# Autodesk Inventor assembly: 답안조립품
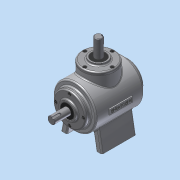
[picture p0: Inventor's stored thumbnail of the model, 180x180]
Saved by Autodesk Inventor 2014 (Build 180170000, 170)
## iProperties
Created: 2015-01
Part Number: 답안조립품
Document SubType Name: Assembly
Designer: user
Author: user
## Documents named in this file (15)
- C:\Users\user\Desktop\450105V1031\답안조립품.iam
- C:\Users\user\Desktop\450105V1031\본체.ipt
- C:\Users\user\Desktop\450105V1031\커버2.ipt
- C:\Users\user\Desktop\450105V1031\M4.ipt
- C:\Users\user\Desktop\450105V1031\서브 축.ipt
- 서브 축.ipt
- C:\Users\user\Desktop\450105V1031\키 4x4.ipt
- C:\Users\user\Desktop\450105V1031\서브 베벨기어.ipt
- C:\Users\user\Desktop\450105V1031\베어링 6203.ipt
- C:\Users\user\Desktop\450105V1031\커버.ipt
- C:\Users\user\Desktop\450105V1031\오일실.ipt
- C:\Users\user\Desktop\450105V1031\메인 축.ipt
- 메인 축.ipt
- C:\Users\user\Desktop\450105V1031\키 5x5.ipt
- C:\Users\user\Desktop\450105V1031\메인 베벨기어.ipt
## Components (12 placed, 1 different names)
1. M4:1
2. M4:2
3. M4:3 — 각도:3
4. M4:4
5. M4:5
6. M4:6
7. M4:7
8. M4:8
9. M4:9 — 각도:6
10. M4:10
11. M4:11
12. M4:12
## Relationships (2: Angle 2)
- 각도:3 [Angle]: M4:3
- 각도:6 [Angle]: M4:9
